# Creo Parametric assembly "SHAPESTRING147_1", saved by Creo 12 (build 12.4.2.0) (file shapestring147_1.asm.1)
Units: Custom; MM, KILOGRAM, SECS

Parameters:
  PTC_WM_ITERATION = "0"
  PTC_WM_VERSION = "-.0"
  PTC_WM_LIFECYCLE_STATE = "In Work"
  PTC_WM_LIFECYCLE = "MO_CADDocument"
  PTC_WM_CREATED_BY = "Maximilian Roepper (Z0017RMS: MO)"
  PTC_WM_CREATED_ON = "18-Sep-26 11:36:42 AM"
  PTC_WM_MODIFIED_BY = "Maximilian Roepper (Z0017RMS: MO)"
  PTC_WM_MODIFIED_ON = "18-Sep-26 11:36:46 AM"
  PDMLINKNUMBER = "PDM000071454968"
  PTC_WM_NUMBER = "PDM000071454968"

Other parameters: WEIGHT, WEIGHT_FACTOR, WEIGHT_ADD, MC_ERRORS, SUPPLIER

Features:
  1. coordinate system
  2. imported feature
  3. component "SHAPESTRING075_1"
  4. component "SHAPESTRING145_1"
  5. component "SHAPESTRING146_1"

Other named items: DRW_VIEW_ORG, ROUGH-GROB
